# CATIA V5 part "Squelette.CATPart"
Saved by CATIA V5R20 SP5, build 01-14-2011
Part number: Squelette
Publications: "A", "E", "D", "Droite AE axe bâti", "Plan sup bâti", "G", "F", "Bielle 7", "Bielle 3", "b", "Bielle 4", "B", "Bielle 1", "Décalage Bielle1"
Bounding box of the stored display mesh (mm): x 0 to 0, y 0 to 180.133, z 56 to 404
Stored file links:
  E:\IAO_2010\iao\IAO_MMS_Groupe2\IAO_MMS_Groupe2\flafosse\Catia\IAO\Squelette.CATPart
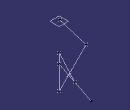
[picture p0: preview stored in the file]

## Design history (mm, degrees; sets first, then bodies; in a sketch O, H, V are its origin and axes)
Body1 (main body)
  Point1 "A": type OnPlane, Support yz-plane, H 0, V 243, Direction (0, 1, 0)
  Point2 "E": type OnPlane, Support yz-plane, H 0, V 56, Direction (0, 1, 0)
  Point3 "D": type OnPlane, Support yz-plane, H 0, V 188, Direction (0, 1, 0)
  Line1 "Droite AE axe bâti": type PtPt, FirstPoint Point1, SecondPoint Point2
  Plane1 "Plan sup bâti": type Offset, RefPlane xy-plane, Offset 396
  Point4 "G": type OnPlane, Support yz-plane, H 4, V 404, Direction (0, 1, 0)
  Point5 "F": type OnPlane, Support yz-plane, H 152, V 358, Direction (0, 1, 0)
  Line2 "Bielle 7": type PtPt, FirstPoint Point5, SecondPoint Point4
  Line3 "Bielle 3": type PtPt, FirstPoint Point5, SecondPoint Point2
  Point6 "b": type OnCurve, Support Line3, Length 220
  Line4 "Bielle 4": type PtPt, FirstPoint Point3, SecondPoint Point6, End 142
  Point7 "B": type OnCurve, Support Line4, Length 98
  Line5 "Bielle 1": type PtPt, FirstPoint Point1, SecondPoint Point7
  Plane2 "Décalage Bielle1": type Offset, RefPlane yz-plane, Offset 10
